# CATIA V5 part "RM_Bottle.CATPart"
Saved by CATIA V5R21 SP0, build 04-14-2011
Part number: RM_Bottle
Material "Plastic": density 1200 kg/m3, Young's modulus 2.2e+09 Pa, Poisson ratio 0.38, thermal expansion 6.84e-05 1/K
Material "Plastic": density 1200 kg/m3, Young's modulus 2.2e+09 Pa, Poisson ratio 0.38, thermal expansion 6.84e-05 1/K
Material "Oil Blue": density 7860 kg/m3, Young's modulus 2e+11 Pa, Poisson ratio 0.266
Bounding box of the stored display mesh (mm): x -40.5 to 40.5, y -40.49 to 40.491, z 0 to 264
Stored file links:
  G:\CATIA\RM_Bottle.CATPart
  C:\Program Files (x86)\Dassault Systemes\B21\intel_a\resources\graphic\figures\CATIA_EnvironmentMap_Road_512x512.jpg
  C:\Program Files (x86)\Dassault Systemes\B21\intel_a\resources\graphic\figures\CATIA_EnvironmentMap_Square1_512x512.jpg
  C:\Program Files (x86)\Dassault Systemes\B21\intel_a\resources\graphic\figures\CATIA_EnvironmentMap_Flat_512x512.jpg
  C:\Program Files (x86)\Dassault Systemes\B21\intel_a\resources\graphic\figures\CATIA_EnvironmentMap_Desert_512x512.jpg
  C:\Program Files (x86)\Dassault Systemes\B21\intel_a\resources\graphic\figures\CATIA_EnvironmentMap_Field_512x512.jpg
  C:\Users\Riad Mahamud Piash\Downloads\adobe-688d333485ef2.jpg
  C:\Program Files (x86)\Dassault Systemes\B21\intel_a\resources\graphic\figures\CATIA_EnvironmentMap_Garden_512x512.jpg
  C:\Program Files (x86)\Dassault Systemes\B21\intel_a\resources\graphic\figures\CATIA_EnvironmentMap_Sunset_512x512.jpg
  C:\Program Files (x86)\Dassault Systemes\B21\intel_a\resources\graphic\figures\CATIA_EnvironmentMap_GridSpot_512x512.jpg
  C:\Program Files (x86)\Dassault Systemes\B21\intel_a\resources\graphic\figures\CATIA_EnvironmentMap_Square2_512x512.jpg
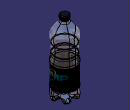
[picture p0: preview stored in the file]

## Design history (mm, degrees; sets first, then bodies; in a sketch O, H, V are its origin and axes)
Body1 (main body), material "Plastic"
  Point1: (0, 0, 0)
  Circle1: type CtrRad, Start 0, End 180, Radius 80, Center Point1, Support xy-plane, FirstDirection (1, 0, 0)
  Point2: (0, 15, 0)
  Point3: (0, 23, 12)
  Point4: (0, 42, 23)
  Point5: (16, 42, 0)
  Point6: (-16, 42, 0)
  Curve1: Elements Body1
  Curve2: Elements Body1
  Point7: (0, 0, 130)
  Circle2: type CtrRad, Start 0, End 180, Radius 80, Center Point7, Support xy-plane, FirstDirection (1, 0, 0)
  Loft1: Sections (Circle1; Circle2)
  Fill1: Boundary Circle1
  Join1: Elements (Loft1; Fill1)
  Fillet1: radius 7, on face of Loft1; face of Fill1
  Sweep1: type Unspec, Profile Curve1, Guide Curve2
  CircPattern1: of Sweep1, instances 5, angular step 72, axis from Z axis
  Trim1: Trimmed (CircPattern1; Fillet1)
  Trim2: Trimmed (Sweep1; Trim1)
  Fillet2: radius 6, on face of CircPattern1 (x4); face of Sweep1
  Point8: (0, 0, 15), relative to Point7
  Circle3: type CtrRad, Start 0, End 180, Radius 70, Center Point8, Support xy-plane, FirstDirection (1, 0, 0)
  Loft2: Sections (Circle2; Circle3)
  Point9: (0, 0, 5), relative to Point8
  Point10: (0, 0, 5)
  Point11: (0, 0, 5), relative to Point9
  Point12: (0, 0, 5), relative to Point11
  Point13: (0, 0, 5), relative to Point12
  Point14: (0, 0, 5), relative to Point13
  Point15: (0, 0, 5), relative to Point14
  Circle4: type CtrRad, Start 0, End 180, Radius 73, Center Point9, Support xy-plane, FirstDirection (1, 0, 0)
  Circle5: type CtrRad, Start 0, End 180, Radius 70, Center Point11, Support xy-plane, FirstDirection (1, 0, 0)
  Circle6: type CtrRad, Start 0, End 180, Radius 73, Center Point12, Support xy-plane, FirstDirection (1, 0, 0)
  Circle7: type CtrRad, Start 0, End 180, Radius 70, Center Point13, Support xy-plane, FirstDirection (1, 0, 0)
  Circle8: type CtrRad, Start 0, End 180, Radius 73, Center Point14, Support xy-plane, FirstDirection (1, 0, 0)
  Circle9: type CtrRad, Start 0, End 180, Radius 70, Center Point15, Support xy-plane, FirstDirection (1, 0, 0)
  Loft3: Sections (Circle3; Circle4; Circle5; Circle6; Circle7; Circle8; Circle9)
  Join2: Elements (Fillet2; Loft2)
  Fillet3: radius 50, on face of Loft2
  Point16: (0, 0, 8), relative to Point15
  Circle10: type CtrRad, Start 0, End 180, Radius 75, Center Point16, Support xy-plane, FirstDirection (1, 0, 0)
  Point17: (0, 0, 12), relative to Point16
  Circle11: type CtrRad, Start 0, End 180, Radius 80, Center Point17, Support xy-plane, FirstDirection (1, 0, 0)
  Point18: (0, 0, 8), relative to Point17
  Circle12: type CtrRad, Start 0, End 180, Radius 80, Center Point18, Support xy-plane, FirstDirection (1, 0, 0)
  Point19: (0, 0, 15), relative to Point18
  Circle13: type CtrRad, Start 0, End 180, Radius 65, Center Point19, Support xy-plane, FirstDirection (1, 0, 0)
  Point20: (0, 0, 25), relative to Point19
  Circle14: type CtrRad, Start 0, End 180, Radius 25, Center Point20, Support xy-plane, FirstDirection (1, 0, 0)
  Loft4: Sections (Circle9; Circle10; Circle11; Circle12; Circle13; Circle14)
  Point21: (0, 0, 8), relative to Point20
  Circle15: type CtrRad, Start 0, End 180, Radius 25, Center Point21, Support xy-plane, FirstDirection (1, 0, 0)
  Loft5: Sections (Circle14; Circle15)
  Fillet4: type BiTangent, Element1 Loft4, Element2 Loft5, Radius 10
  Sweep2: type Circle, Guide Circle15, Radius 1.5, Angle1 0, Angle2 45
  Point22: (0, 0, 13), relative to Point21
  Circle16: type CtrRad, Start 0, End 180, Radius 25, Center Point22, Support xy-plane, FirstDirection (1, 0, 0)
  Loft6: Sections (Circle15; Circle16)
  Point23: (0, 12.5, 2), relative to Point21
  Helix1: Direction Z axis, RefPoint Point23, Pitch 3, Height 10, TaperAngle 0
  Sweep3: type Circle, Guide Helix1, Radius 1
  Join3: Elements (Fillet4; Fillet3; Loft3)
  Fillet5: radius 5, on face of Loft4; face of Fillet3
Body2, material "Oil Blue"
  Circle17: type CtrRad, Start 0, End 180, Radius 29, Center Point22, Support xy-plane, FirstDirection (1, 0, 0)
  Extrude1: Lim1 11, Lim2 0, Direction (0, 0, 1), Element1 Circle17
  Fill2: Boundary Circle17
  Join4: Elements (Extrude1; Fill2)
  Fillet6: radius 2, on face of Extrude1
  Point24: type OnCurve, Support edge of Extrude1, RefPoint {extremum Reference edge of Extrude1, Direction (1, 2, 3)}, Length 0
  Point25: (0, 0, 1), relative to Point24
  Point26: (0, 0, 8), relative to Point25
  Line1: type PtPt, FirstPoint Point26, SecondPoint Point25
  Sweep4: type Circle, Guide Line1, Radius 0.25
  CircPattern2: of Sweep4, instances 100, angular step 3.6 {= 360.0*1 deg/CircPattern2.AngularNumber}, axis from Z axis
Body3, material "Plastic"
  Point27: (0, 0, 40), relative to Point1
  Circle18: type CtrRad, Start 0, End 180, Radius 80, Center Point27, Support xy-plane, FirstDirection (1, 0, 0)
  Point28: (0, 0, 75), relative to Point27
  Circle19: type CtrRad, Start 0, End 180, Radius 80, Center Point28, Support xy-plane, FirstDirection (1, 0, 0)
  Loft7: Sections (Circle18; Circle19)
  Set1
    ThickSurface1: BotOffset 0, Surface Loft7, TopOffset 0.5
